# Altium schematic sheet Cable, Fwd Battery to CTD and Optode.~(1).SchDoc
size Tabloid; Organization: Monterey Bay Aquarium Research Institute; Address1: 7700 Sandholdt Rd; Address2: Moss Landing, CA 95039-9644; CompanyName: MBARI
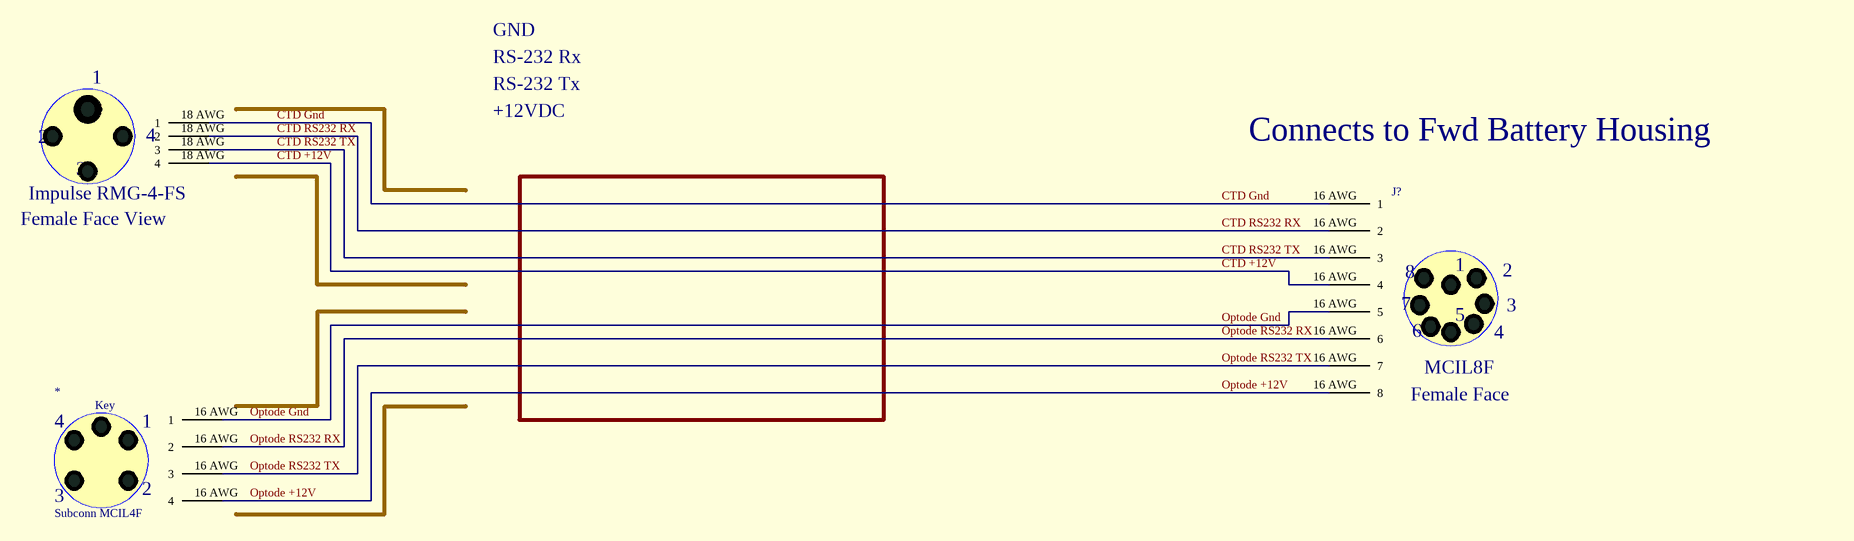
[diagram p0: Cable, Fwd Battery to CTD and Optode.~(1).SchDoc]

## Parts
*  Subconn MCIL4F
?  Impulse RMG-4-FS  [None Available]
J?  MCIL8F  View: Female Face

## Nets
CTD +12V: ?.18_AWG(4) J?.16_AWG(4)
CTD Gnd: ?.18_AWG(1) J?.16_AWG(1)
CTD RS232 RX: ?.18_AWG(2) J?.16_AWG(2)
CTD RS232 TX: ?.18_AWG(3) J?.16_AWG(3)
Optode +12V: *.16_AWG(4) J?.16_AWG(8)
Optode Gnd: *.16_AWG(1) J?.16_AWG(5)
Optode RS232 RX: *.16_AWG(2) J?.16_AWG(6)
Optode RS232 TX: *.16_AWG(3) J?.16_AWG(7)

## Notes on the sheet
- GND
- RS-232 Rx
- RS-232 Tx
- +12VDC
- Connects to Fwd Battery Housing
- Female Face View

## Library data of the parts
* = Subconn MCIL4F: Subconn MCIL4F Connector
? = IMPULSE-RMG-4-FS-REVERSE
J? = SUBCONN-MCxx8F: Subconn MCIL8F Connector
